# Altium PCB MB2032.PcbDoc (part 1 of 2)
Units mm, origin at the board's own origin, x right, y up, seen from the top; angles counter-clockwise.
Board outline 43.1 x 54.35 mm, 4 copper layers (Top Layer, Internal 1, Internal 2, Bottom Layer), stack 1.614 mm thick; 112 components, 86 nets, 372 pads, 581 vias.
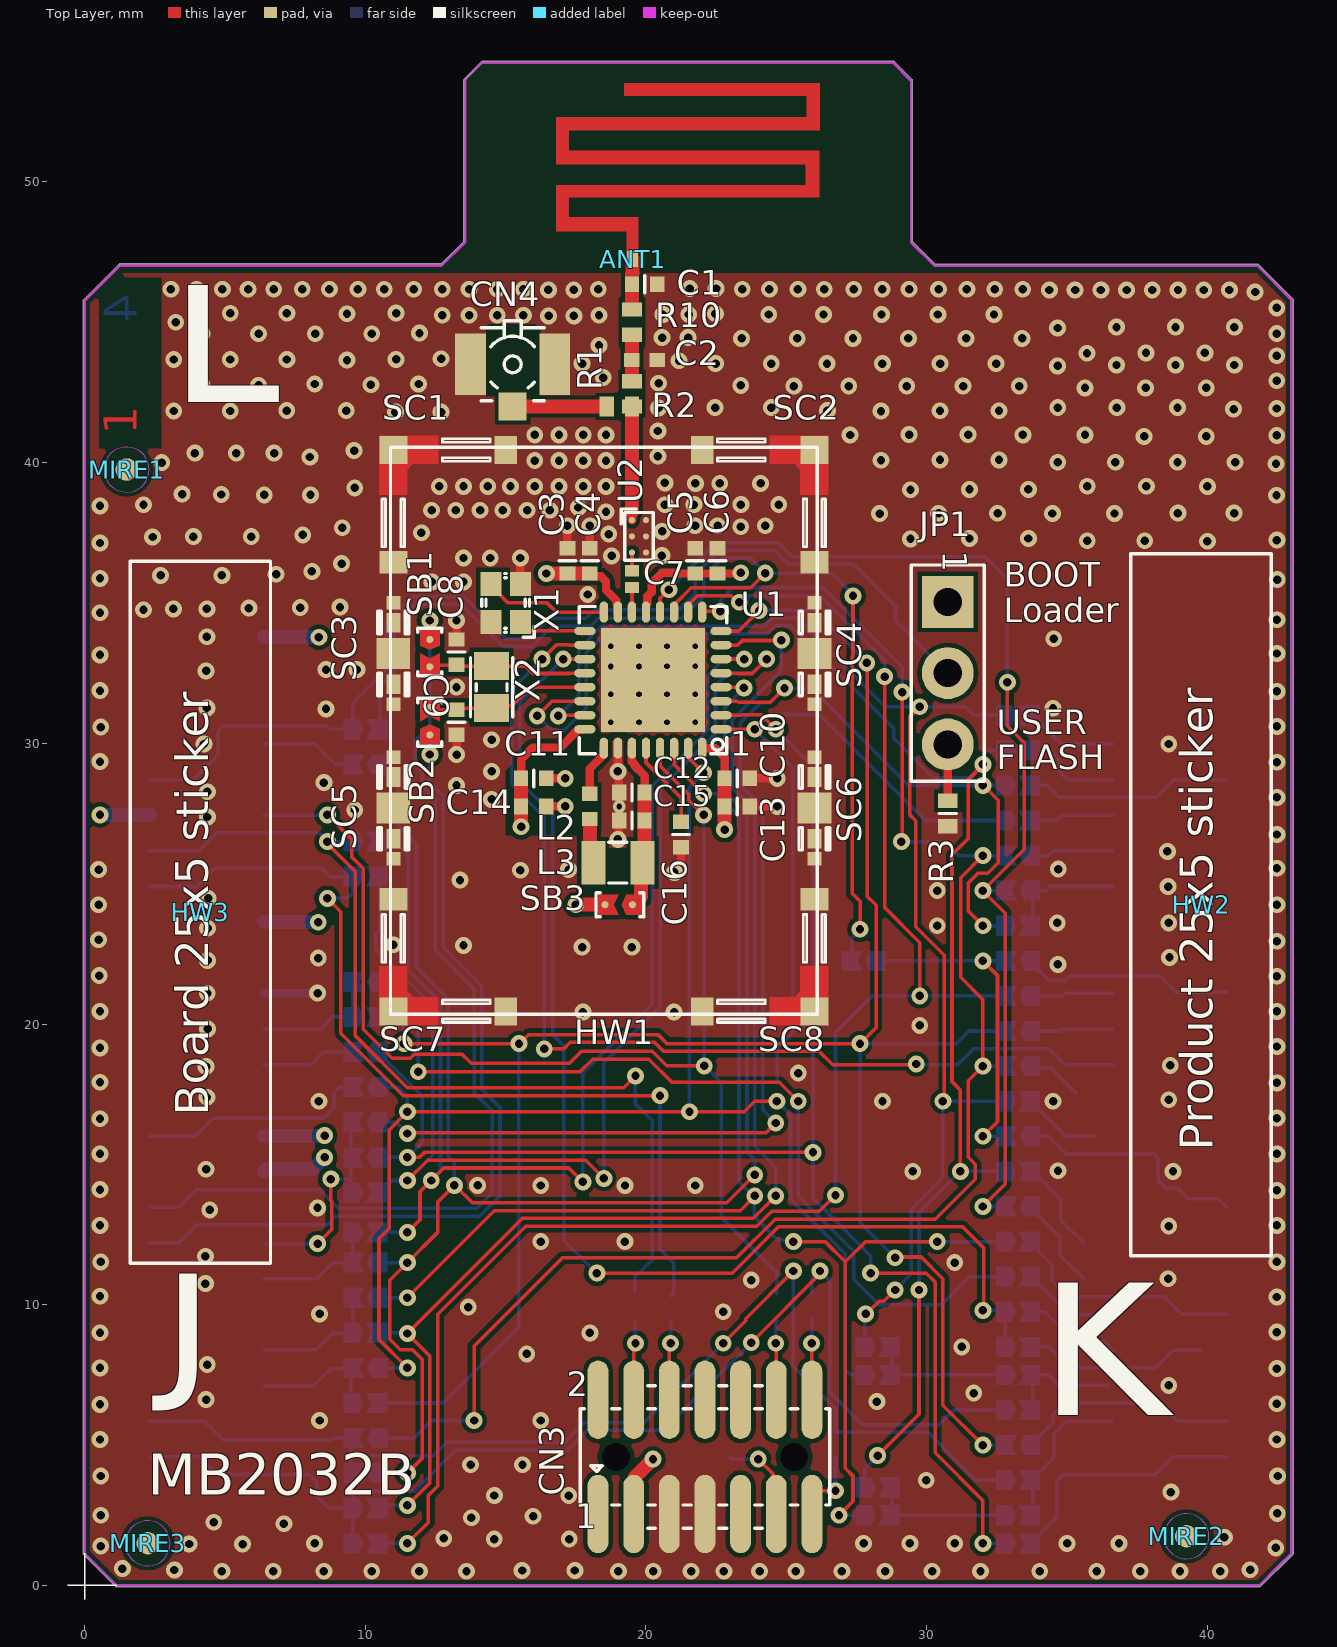
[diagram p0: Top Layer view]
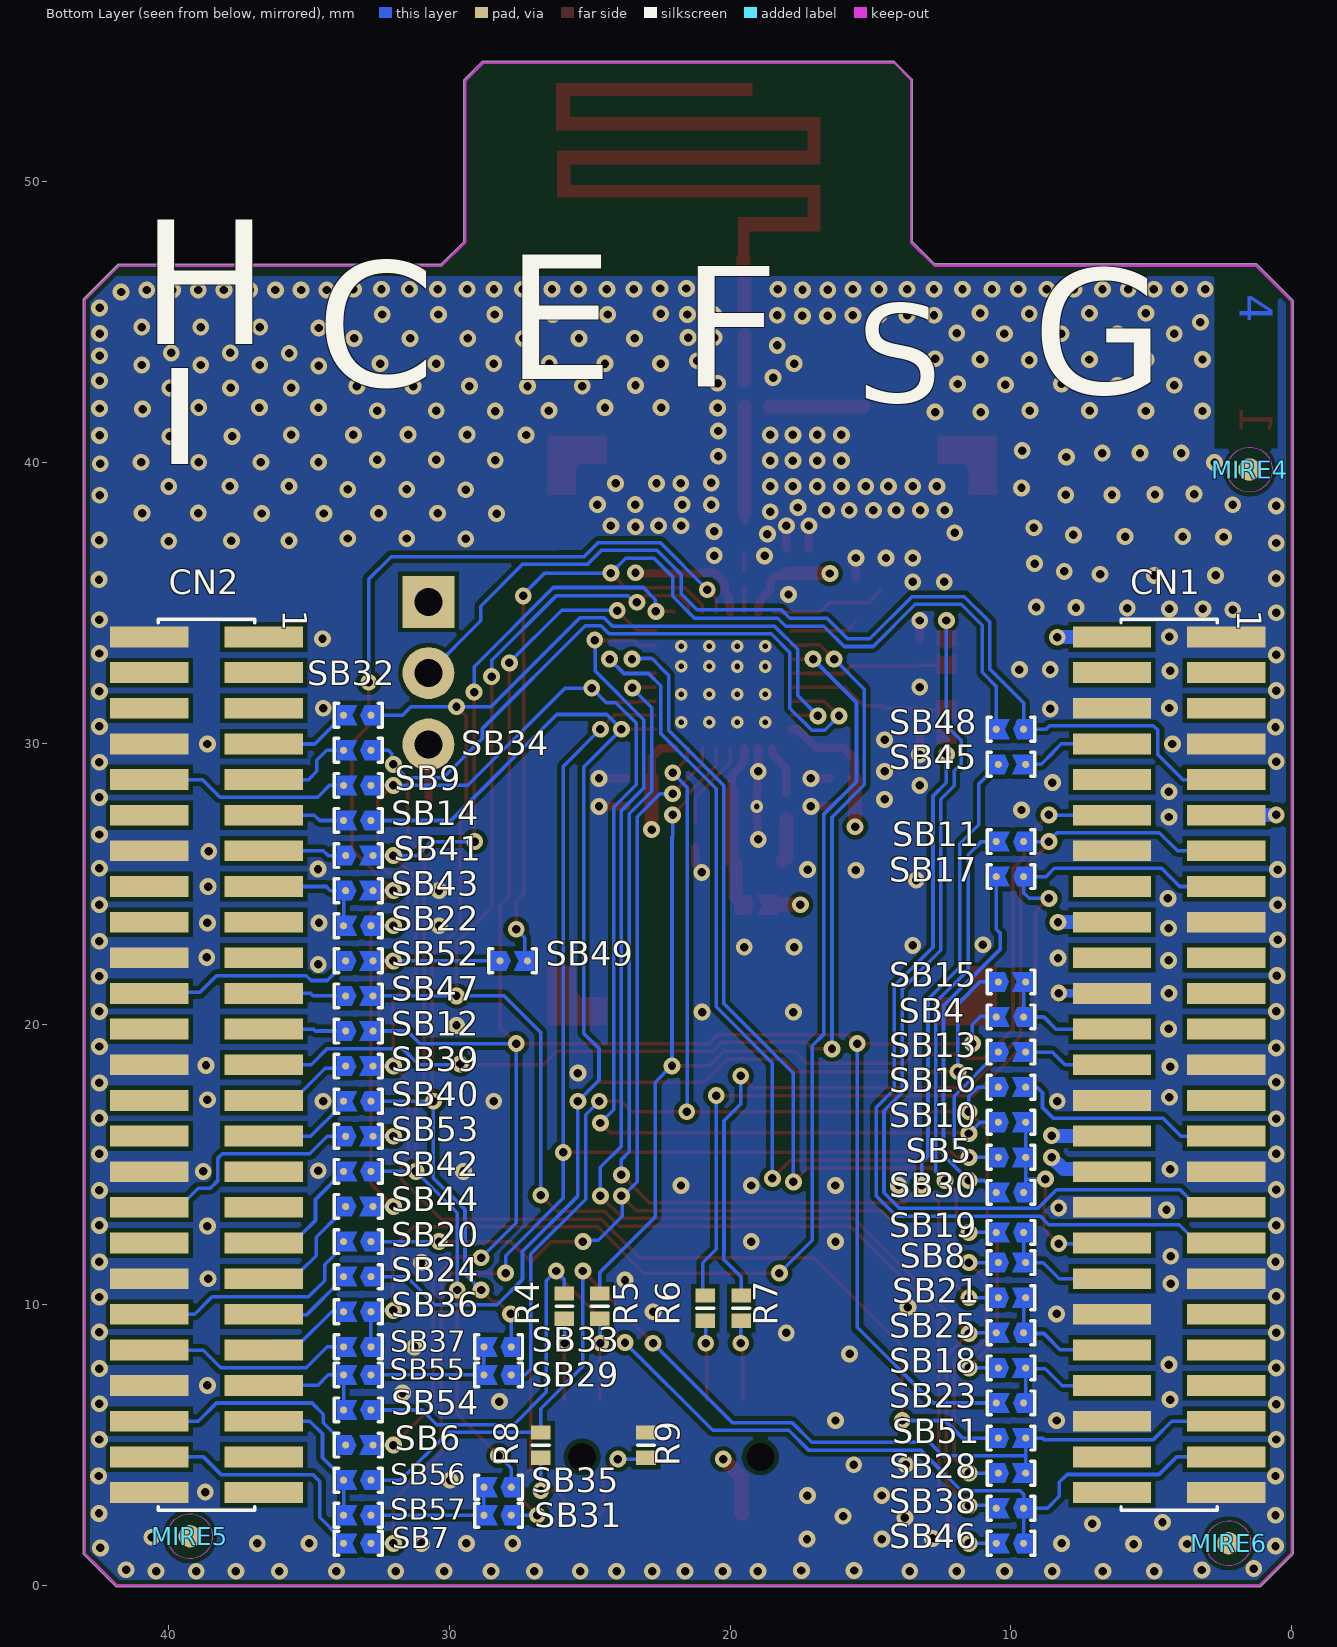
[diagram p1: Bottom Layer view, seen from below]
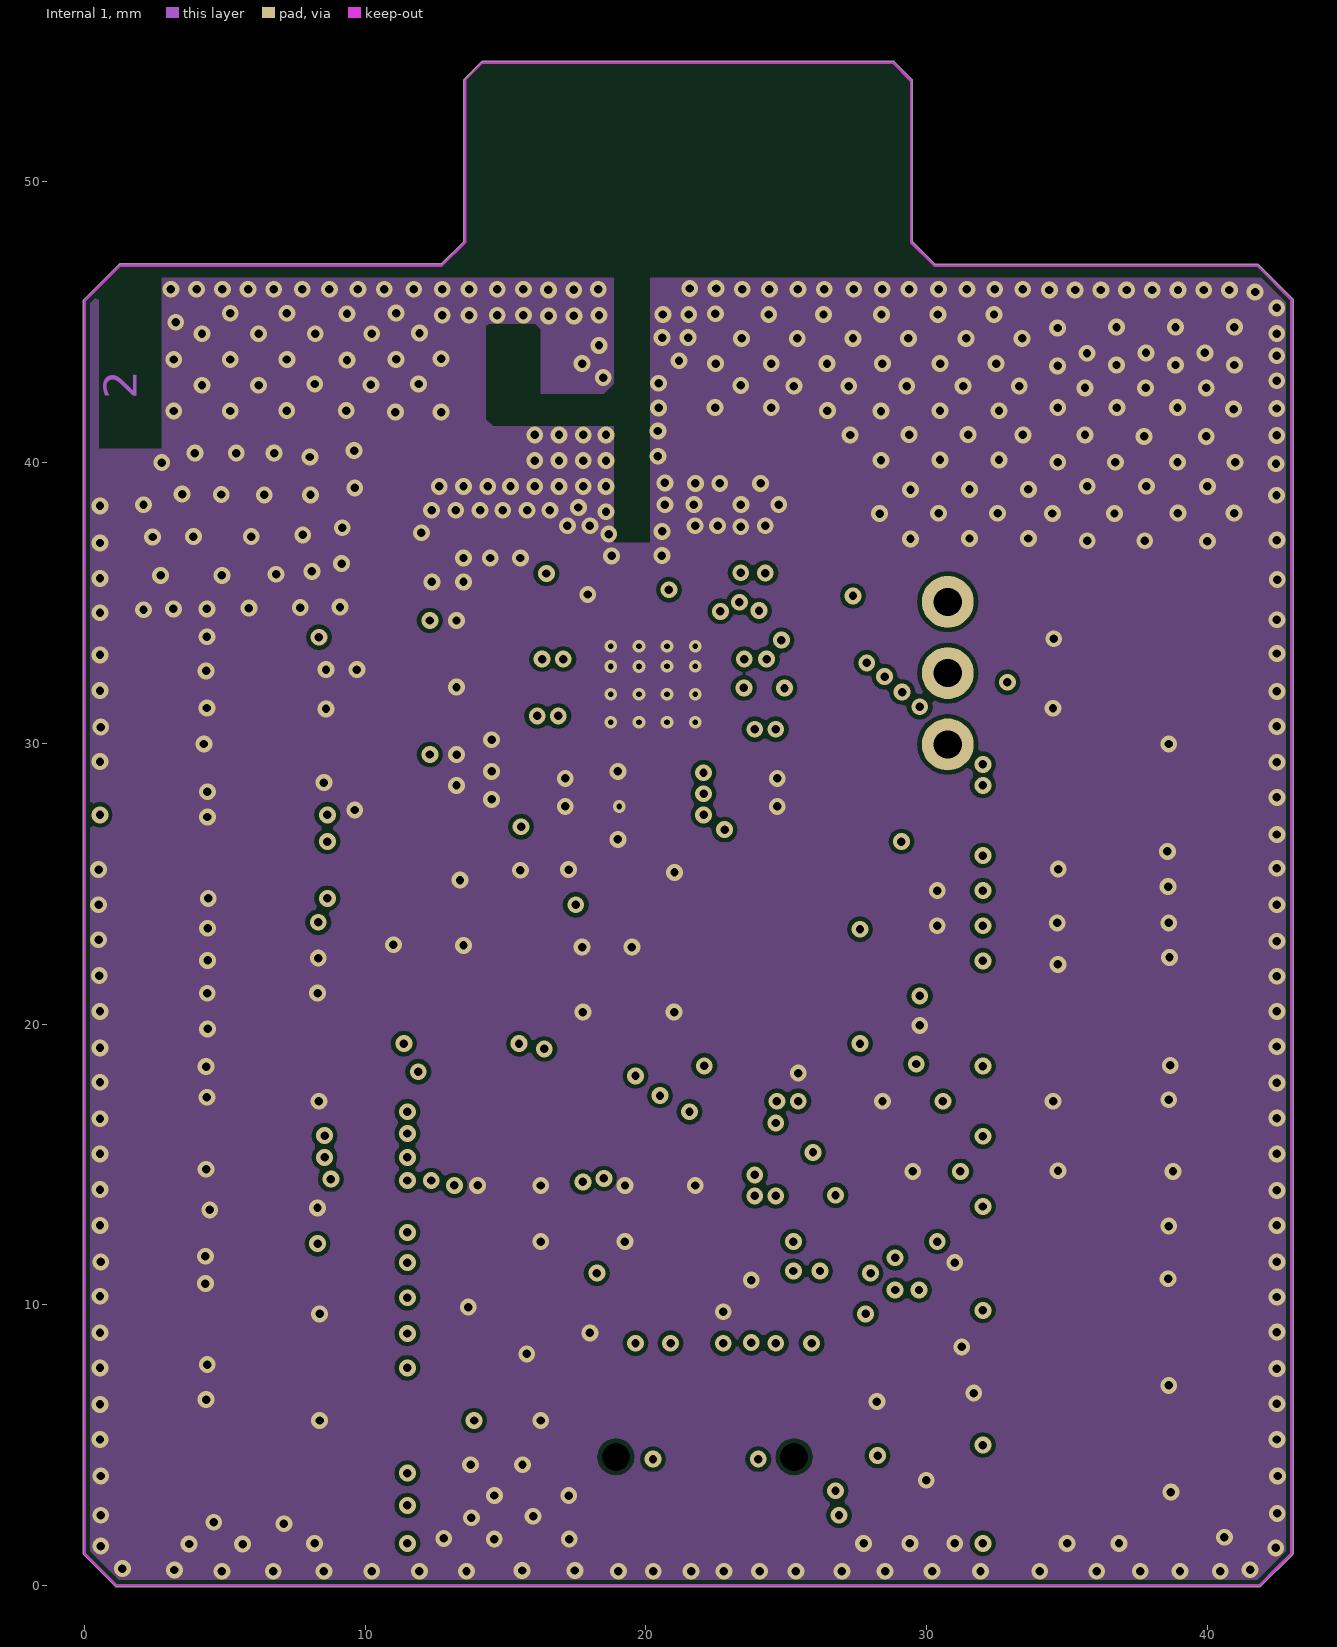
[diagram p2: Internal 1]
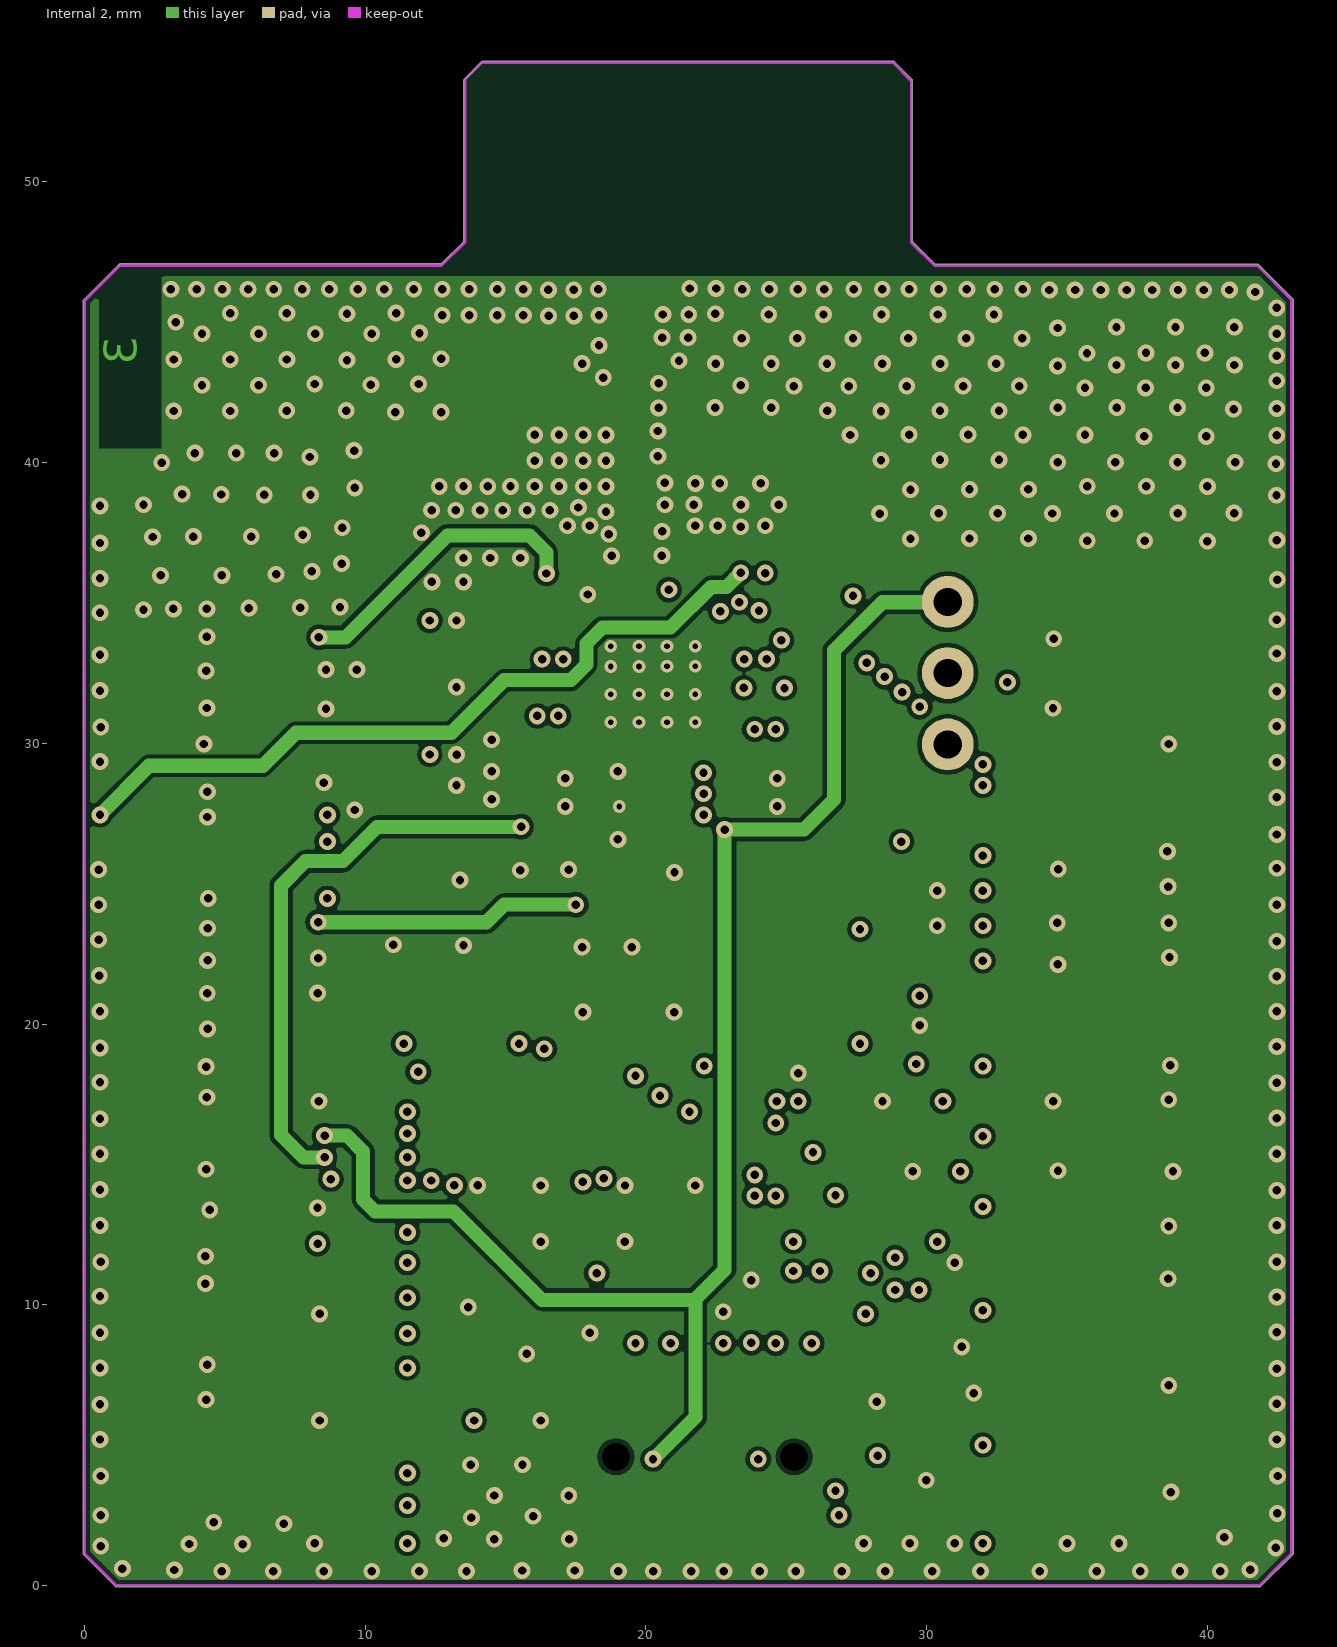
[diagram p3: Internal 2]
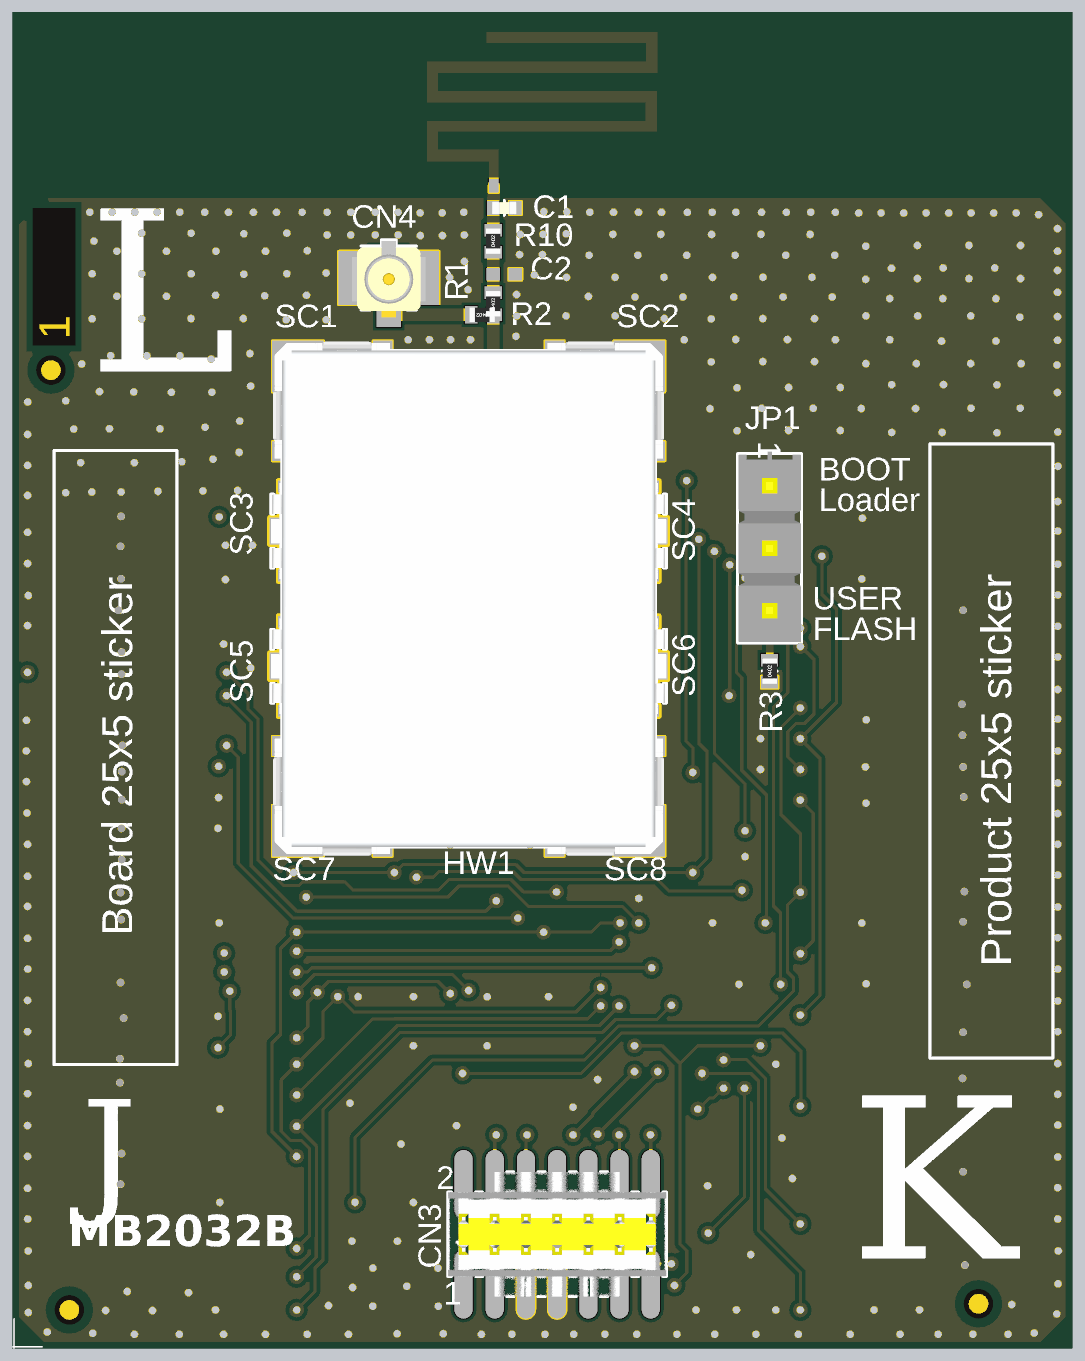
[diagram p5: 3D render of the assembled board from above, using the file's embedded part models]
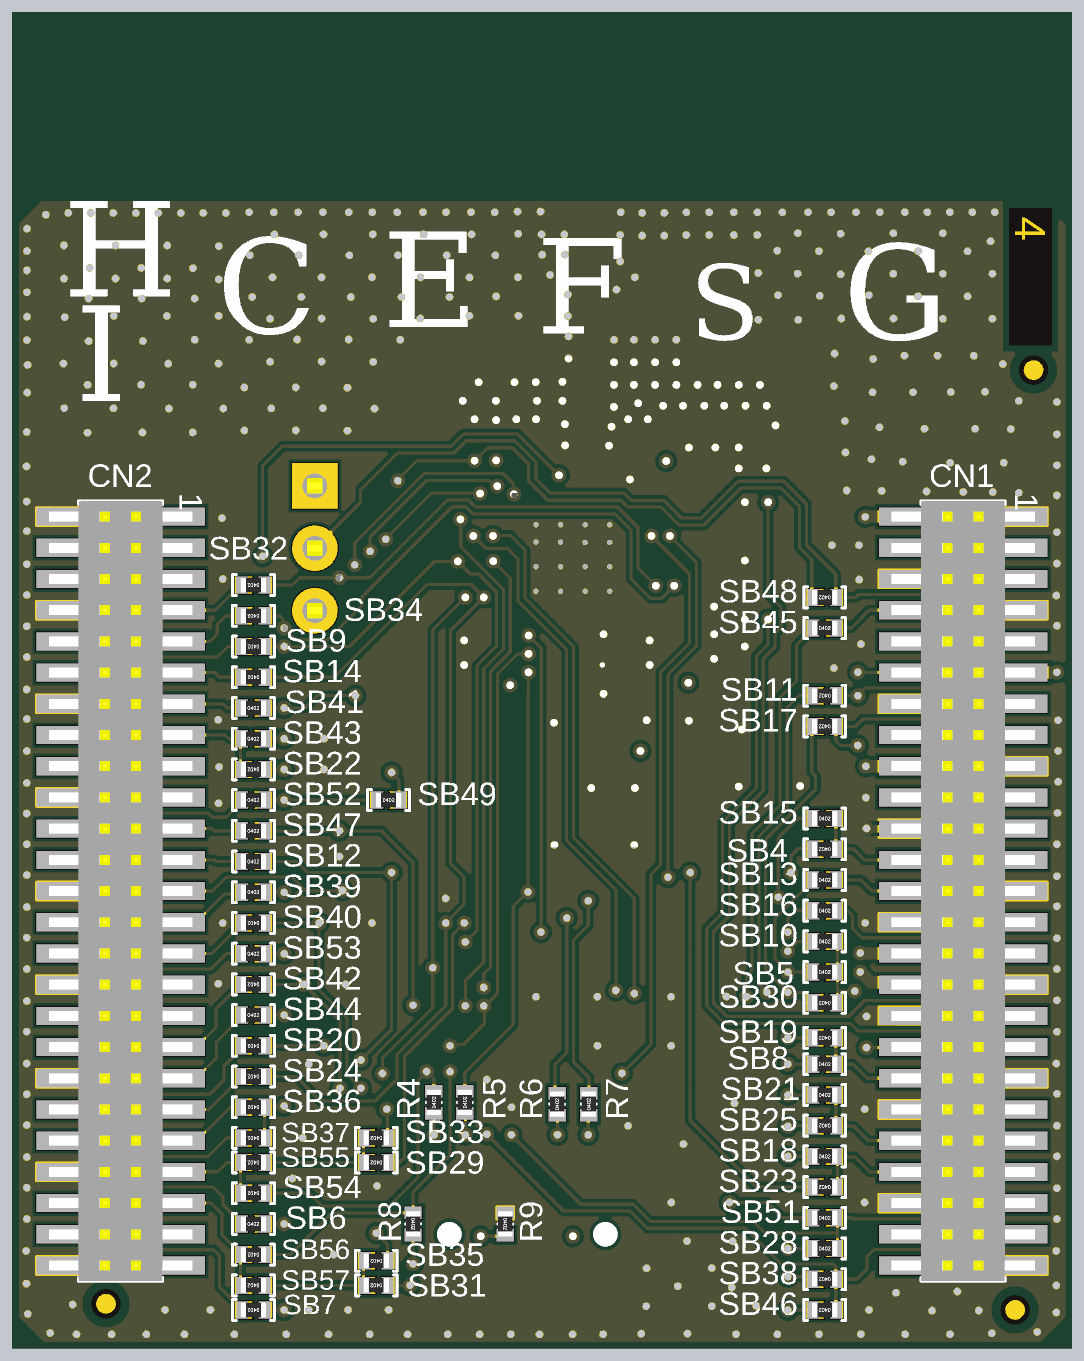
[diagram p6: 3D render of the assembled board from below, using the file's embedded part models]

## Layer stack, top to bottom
Top Solder: solder mask 0.015, Solder Resist, Dk 3.5
Top Layer: signal copper 0.042
Dielectric 1: core 0.106, FR-4, Dk 4.2
Internal 1: signal copper 0.035
Dielectric 3: prepreg 1.248, Dk 4.2
Internal 2: signal copper 0.035
Dielectric 2: core 0.106, Dk 4.2
Bottom Layer: signal copper 0.042
Bottom Solder: solder mask 0.015, Solder Resist, Dk 3.5

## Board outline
-0.05,1.139 -0.05,45.75 -0.05,45.755 cw(c0,45.755) -0.035,45.791 1.209,47.036 cw(c1.245,47) 1.218,47.042 cw(c1.26,47.015) 1.225,47.051 1.246,47.072 cw(c1.282,47.037) 1.282,47.087 12.721,47.087 13.512,47.878 13.512,53.615 cw(c13.563,53.615) 13.527,53.651 14.162,54.285 cw(c14.197,54.25) 14.198,54.3 28.803,54.3 cw(c28.803,54.25) 28.838,54.285 29.473,53.651 cw(c29.438,53.615) 29.488,53.615 29.488,47.876 30.293,47.071 cw(c30.257,47.035) 30.298,47.066 41.78,47.066 cw(c41.78,47.015) 41.816,47.051 43.03,45.837 cw(c43.001,45.795) 43.051,45.795 cw(c43.001,45.795) 43.05,45.785 43.05,1.151 cw(c43.001,1.141) 43.051,1.141 cw(c43.001,1.141) 43.037,1.105 41.888,-0.036 cw(c41.852,0) 41.852,-0.05 1.139,-0.05 cw(c1.139,0) 1.103,-0.036 -0.036,1.103 cw(c0,1.139)

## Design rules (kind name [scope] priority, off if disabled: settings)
Clearance RF_C4 [InNet('NetC4_1') or  InNet('NetC4_2') vs InNet('GND')] p1: gap=0.1 ignorepadtopadclearanceinfootprint=FALSE except(0.145: Arc-Text Track-Text SMDPad-SMDPad SMDPad-THPad SMDPad-Via SMDPad-Text THPad-THPad THPad-Via THPad-Text Via-Via Via-Text Fill-Text Poly-Text Region-Text Text-Text; 0.2: Arc-Hole Track-Hole SMDPad-Hole THPad-Hole Via-Hole Fill-Hole Poly-Hole Region-Hole Text-Hole)
Clearance RF_signals [InNetClass('NC_SINGLE_50_OHMS') vs InNet('GND')] p2: gap=0.145 ignorepadtopadclearanceinfootprint=FALSE except(0.138: Arc-Fill Arc-Poly Arc-Region Track-Fill Track-Poly Track-Region; 0.2: Arc-Hole Track-Hole SMDPad-Hole THPad-Hole Via-Hole Fill-Hole Poly-Hole Region-Hole Text-Hole)
Clearance [All] p3: gap=0.15 ignorepadtopadclearanceinfootprint=FALSE
ComponentClearance [All] p1: gap=0.2 collisioncheckmode=3 verticalgap=0.2 showdistances=FALSE
HoleSize [All] p1: absolutevalues=TRUE maxlimit=10 minlimit=0.025 maxpercent=80.000 minpercent=20.000
MinimumSolderMaskSliver [All] p1: minsoldermaskwidth=0.1
PlaneConnect [All] p1: planeconnectstyle=Relief reliefexpansion=0.508 reliefentries=4 reliefconductorwidth=0.21 reliefairgap=0.21
PolygonConnect PolygonConnect_via [IsVia] p1: connectstyle=Direct reliefconductorwidth=0.254 reliefentries=4 polygonreliefangle="90 Angle" airgapwidth=0.254
PolygonConnect General [All] p2: connectstyle=Direct reliefconductorwidth=0.2 reliefentries=4 polygonreliefangle="90 Angle" airgapwidth=0.2
RoutingVias [All] p1: holewidth=0.3 width=0.6 viastyle="Through Hole" minholewidth=0.2 minwidth=0.5 maxholewidth=3.5 maxwidth=6.5
SilkToSilkClearance [All] p1: silktosilkclearance=0.2
SilkToSolderMaskClearance [IsPad] p1: minsilkscreentomaskgap=0.2 clearancetoexposedcopper=TRUE
SolderMaskExpansion [All] p1: expansion=0.102 istentingtop=FALSE
Width Width_RF [InNetClass('NC_SINGLE_50_OHMS')] p1: maxlimit=0.5 minlimit=0.254 preferedwidth=0.254 toplayer_minwidth=0.28 toplayer_prefwidth=0.5 impedanceprofiledriven=TRUE minimp=50.000000 maximp=50.000000 favimp=50.000000
Width [All] p2: maxlimit=6 minlimit=0.127 preferedwidth=0.5 toplayer_prefwidth=0.127 midlayer1_minwidth=0.21 midlayer1_maxwidth=0.8 midlayer1_prefwidth=0.254 midlayer2_minwidth=0.21 midlayer2_maxwidth=0.8 bottomlayer_prefwidth=0.127 minimp=50.000000 maximp=50.000000 favimp=50.000000
24 further rules are at their usual default settings.

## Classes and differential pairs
net class NC_SINGLE_50_OHMS: NetANT1_1 NetC2_2 NetCN4_1 NetR1_1
component class U_RF: ANT1 C1 C2 C3 C4 C7 CN4 HW1 R1 R2 R10 SC1 SC2 SC3 SC4 SC5 SC6 SC7 SC8 U1 U2 X1
component class U_Connectors: CN1 CN2 SB52 SB53 SB54 SB55 SB56 SB57
component class U_MCU: C8 C9 CN3 JP1 R3 R4 R5 R6 R7 R8 R9 SB1 SB2 SB4 SB5 SB6 SB7 SB8 SB9 SB10 SB11 SB12 SB13 SB14 SB15 SB16 SB17 SB18 SB19 SB20 SB21 SB22 SB23 SB24 SB25 SB28 SB29 SB30 SB31 SB32 SB33 SB34 SB35 SB36 SB37 SB38 SB39 SB40 SB41 SB42 SB43 SB44 SB45 SB46 SB47 SB48 SB49 SB51 X2
component class U_Power_Supply: C5 C6 C10 C11 C12 C13 C14 C15 C16 L2 L3 SB3
component class Project_Overview: HW2 HW3

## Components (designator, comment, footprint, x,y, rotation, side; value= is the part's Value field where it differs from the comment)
ANT1 "2.4GHz_BT_ANT" ANT_BT_BNRG_2P4GHZ_MB2032 19.38,47.25 r90 top value=2.4GHZ_BNRG_ANT
C1 "Capacitor" C0402 19.95,46.35 r180 top value=6.8pF
C2 "Capacitor" C0402_MURATA_GRM155_H0P5 19.95,43.65 r180 top value=0.9pF
C3 "Capacitor" C0402 17.2,36.5 r270 top value=100nF
C4 "Capacitor" C0402 18,36.5 r270 top value=3pF
C5 "Capacitor" C0402 21.75,36.5 r270 top value=3pF
C6 "Capacitor" C0402 22.55,36.5 r270 top value=100nF
C7 "Capacitor" C0201_H0P3 19.5,35.85 r90 top value=20pF
C8 "Capacitor" C0402 13.25,33.25 r270 top value=10pF
C9 "Capacitor" C0402 13.25,30.75 r270 top value=10pF
C10 "Capacitor" C0402 23.25,28.75 r180 top value=100nF
C11 "Capacitor" C0402 16,28.75 r180 top value=100nF
C12 "Capacitor" C0402 19.5,28.25 r0 top value=100nF
C13 "Capacitor" C0402 23.25,27.75 r180 top value=1uF
C14 "Capacitor" C0402 16,27.75 r180 top value=4.7uF
C15 "Capacitor" C0402 19.5,27.25 r0 top value=4.7uF
C16 "Capacitor" C0402 21.25,26.75 r90 top value=0.22uF
CN1 "FTSH-125-02-L-DV" CON_SAMTEC_FTSH-125-02-L-DV 4.366,18.548 r270 bottom value="Header 25x2"
CN2 "FTSH-125-02-L-DV" CON_SAMTEC_FTSH-125-02-L-DV 38.656,18.548 r270 bottom value="Header 25x2"
CN3 "Header 7x2" CON_SAMTEC_FTSH-107-01-L-DV-K-A 22.101,4.579 r0 top
CN4 "U.FL-R-SMT-1" CON_HRS_U.FL-R-SMT-1 15.25,43.5 r0 top value=Con_RF_U.FL-R-SMT-1
Designator1 "Comment" IMPEDANCE_TABLE -4.013,161.315 r0 top
Designator2 "Comment" PCB_SPECIFICATIONS -3.124,121.133 r0 top
Designator3 "Comment" Sheetbox_4L2S 51.892,-13.183 r0 top
HW1 "S02-20150300" SHIELD_HARWIN_S02-20150300_15X20_H3 18.5,30.45 r0 top
HW2 "STICKER_PRODUCT" STICKER_PRODUCT_25X5 39.775,24.249 r90 top value="Sticker product"
HW3 "STICKER_BOARD" STICKER_BOARD_25X5 4.126,23.98 r90 top value="Sticker board"
JP1 "Jumper_Header 3x1 Fitted 2-3" CON_SAMTEC_TSW-103-07-F-S 30.75,32.5 r270 top value="Header 3x1"
L2 "Inductor" C0402 18,27.75 r90 top value=22nH
L3 "Inductor" IND_0805_MURATA_LQM21 19,25.75 r180 top value=10uH
MIRE1 "Comment" MIRE_PLACE_SMD_0P8MM 1.5,39.75 r0 top
MIRE2 "Comment" MIRE_PLACE_SMD_0P8MM 39.25,1.75 r0 top
MIRE3 "Comment" MIRE_PLACE_SMD_0P8MM 2.25,1.5 r0 top
MIRE4 "Comment" MIRE_PLACE_SMD_0P8MM 1.5,39.75 r0 bottom
MIRE5 "Comment" MIRE_PLACE_SMD_0P8MM 39.25,1.75 r0 bottom
MIRE6 "Comment" MIRE_PLACE_SMD_0P8MM 2.25,1.5 r0 bottom
R1 "Resistor" R0402 19.5,42.45 r90 top value=0R
R2 "Resistor" r0402 19.05,42 r180 top value=0R
R3 "Resistor" R0402 30.75,27.5 r90 top value=100K
R4 "Resistor" R0402 25.909,9.947 r90 bottom value=47R
R5 "Resistor" R0402 24.651,9.947 r90 bottom value=47R
R6 "Resistor" R0402 20.887,9.878 r90 bottom value=47R
R7 "Resistor" R0402 19.605,9.878 r90 bottom value=47R
R8 "Resistor" R0402 26.75,5 r270 bottom value=47R
R9 "Resistor" R0402 23,5 r270 bottom value=100R
R10 "Resistor" R0402 19.5,45 r90 top value=0R
SB1 "SB_ON" SOLDER-BRIDGE_R0402-0R 12.3,33.25 r270 top value="0 ohm"
SB2 "SB_ON" SOLDER-BRIDGE_R0402-0R 12.3,30.75 r90 top value="0 ohm"
SB3 "SB_ON" SOLDER-BRIDGE_R0402-0R 19.069,24.25 r180 top
SB4 "SB_ON" SOLDER-BRIDGE_R0402-0R 10,20.25 r0 bottom value="0 ohm"
SB5 "SB_ON" SOLDER-BRIDGE_R0402-0R 10,15.25 r180 bottom value="0 ohm"
SB6 "SB_ON" SOLDER-BRIDGE_R0402-0R 33.25,5 r180 bottom value="0 ohm"
SB7 "SB_ON" SOLDER-BRIDGE_R0402-0R 33.25,1.5 r0 bottom value="0 ohm"
SB8 "SB_ON" SOLDER-BRIDGE_R0402-0R 10,11.5 r180 bottom value="0 ohm"
SB9 "SB_ON" SOLDER-BRIDGE_R0402-0R 33.25,28.5 r0 bottom value="0 ohm"
SB10 "SB_ON" SOLDER-BRIDGE_R0402-0R 10,16.5 r180 bottom value="0 ohm"
SB11 "SB_ON" SOLDER-BRIDGE_R0402-0R 10,26.5 r0 bottom value="0 ohm"
SB12 "SB_ON" SOLDER-BRIDGE_R0402-0R 33.25,19.75 r180 bottom value="0 ohm"
SB13 "SB_ON" SOLDER-BRIDGE_R0402-0R 10,19 r180 bottom value="0 ohm"
SB14 "SB_ON" SOLDER-BRIDGE_R0402-0R 33.25,27.25 r0 bottom value="0 ohm"
SB15 "SB_ON" SOLDER-BRIDGE_R0402-0R 10,21.5 r180 bottom value="0 ohm"
SB16 "SB_ON" SOLDER-BRIDGE_R0402-0R 10,17.75 r180 bottom value="0 ohm"
SB17 "SB_ON" SOLDER-BRIDGE_R0402-0R 10,25.25 r0 bottom value="0 ohm"
SB18 "SB_ON" SOLDER-BRIDGE_R0402-0R 10,7.75 r180 bottom value="0 ohm"
SB19 "SB_ON" SOLDER-BRIDGE_R0402-0R 10,12.575 r0 bottom value="0 ohm"
SB20 "SB_ON" SOLDER-BRIDGE_R0402-0R 33.25,12.25 r0 bottom value="0 ohm"
SB21 "SB_ON" SOLDER-BRIDGE_R0402-0R 10,10.25 r180 bottom value="0 ohm"
SB22 "SB_ON" SOLDER-BRIDGE_R0402-0R 33.25,23.5 r0 bottom value="0 ohm"
SB23 "SB_ON" SOLDER-BRIDGE_R0402-0R 10,6.5 r0 bottom value="0 ohm"
SB24 "SB_ON" SOLDER-BRIDGE_R0402-0R 33.25,11 r0 bottom value="0 ohm"
SB25 "SB_ON" SOLDER-BRIDGE_R0402-0R 10,9 r0 bottom value="0 ohm"
SB28 "SB_ON" SOLDER-BRIDGE_R0402-0R 10,4 r180 bottom value="0 ohm"
SB29 "SB_ON" SOLDER-BRIDGE_R0402-0R 28.25,7.5 r0 bottom value="0 ohm"
SB30 "SB_ON" SOLDER-BRIDGE_R0402-0R 10,14 r0 bottom value="0 ohm"
SB31 "SB_ON" SOLDER-BRIDGE_R0402-0R 28.25,2.5 r0 bottom value="0 ohm"
SB32 "SB_ON" SOLDER-BRIDGE_R0402-0R 33.25,31 r0 bottom value="0 ohm"
SB33 "SB_ON" SOLDER-BRIDGE_R0402-0R 28.25,8.5 r0 bottom value="0 ohm"
SB34 "SB_ON" SOLDER-BRIDGE_R0402-0R 33.25,29.75 r0 bottom value="0 ohm"
SB35 "SB_ON" SOLDER-BRIDGE_R0402-0R 28.25,3.5 r0 bottom value="0 ohm"
SB36 "SB_ON" SOLDER-BRIDGE_R0402-0R 33.25,9.75 r0 bottom value="0 ohm"
SB37 "SB_ON" SOLDER-BRIDGE_R0402-0R 33.25,8.5 r0 bottom value="0 ohm"
SB38 "SB_ON" SOLDER-BRIDGE_R0402-0R 10,2.75 r0 bottom value="0 ohm"
SB39 "SB_ON" SOLDER-BRIDGE_R0402-0R 33.25,18.5 r180 bottom value="0 ohm"
SB40 "SB_ON" SOLDER-BRIDGE_R0402-0R 33.25,17.25 r0 bottom value="0 ohm"
SB41 "SB_ON" SOLDER-BRIDGE_R0402-0R 33.25,26 r180 bottom value="0 ohm"
SB42 "SB_ON" SOLDER-BRIDGE_R0402-0R 33.25,14.75 r0 bottom value="0 ohm"
SB43 "SB_ON" SOLDER-BRIDGE_R0402-0R 33.25,24.75 r180 bottom value="0 ohm"
SB44 "SB_ON" SOLDER-BRIDGE_R0402-0R 33.25,13.5 r180 bottom value="0 ohm"
SB45 "SB_ON" SOLDER-BRIDGE_R0402-0R 10,29.25 r180 bottom value="0 ohm"
SB46 "SB_ON" SOLDER-BRIDGE_R0402-0R 10,1.5 r0 bottom value="0 ohm"
SB47 "SB_ON" SOLDER-BRIDGE_R0402-0R 33.25,21 r180 bottom value="0 ohm"
SB48 "SB_ON" SOLDER-BRIDGE_R0402-0R 10,30.5 r0 bottom value="0 ohm"
SB49 "SB_ON" SOLDER-BRIDGE_R0402-0R 27.75,22.25 r180 bottom value="0 ohm"
SB51 "SB_ON" SOLDER-BRIDGE_R0402-0R 10,5.25 r180 bottom value="0 ohm"
SB52 "SB_ON" SOLDER-BRIDGE_R0402-0R 33.25,22.25 r180 bottom value="0 ohm"
SB53 "SB_ON" SOLDER-BRIDGE_R0402-0R 33.25,16 r180 bottom value="0 ohm"
SB54 "SB_ON" SOLDER-BRIDGE_R0402-0R 33.25,6.25 r0 bottom value="0 ohm"
SB55 "SB_ON" SOLDER-BRIDGE_R0402-0R 33.25,7.5 r0 bottom value="0 ohm"
SB56 "SB_ON" SOLDER-BRIDGE_R0402-0R 33.25,3.75 r0 bottom value="0 ohm"
SB57 "SB_ON" SOLDER-BRIDGE_R0402-0R 33.25,2.5 r0 bottom value="0 ohm"
SC1 "Shield-clip_S0951-46R" CLIP_HARWIN_S0981-46R 11,40.45 r180 top value=S0981-46R
SC2 "Shield-clip_S0951-46R" CLIP_HARWIN_S0981-46R 26,40.45 r90 top value=S0981-46R
SC3 "Shield-clip_S0951-46R" CLIP_HARWIN_S0951-46R 11,33.2 r90 top value=S0951-46R
SC4 "Shield-clip_S0951-46R" CLIP_HARWIN_S0951-46R 26,33.2 r90 top value=S0951-46R
SC5 "Shield-clip_S0951-46R" CLIP_HARWIN_S0951-46R 11,27.7 r90 top value=S0951-46R
SC6 "Shield-clip_S0951-46R" CLIP_HARWIN_S0951-46R 26,27.7 r90 top value=S0951-46R
SC7 "Shield-clip_S0951-46R" CLIP_HARWIN_S0981-46R 11,20.45 r270 top value=S0981-46R
SC8 "Shield-clip_S0951-46R" CLIP_HARWIN_S0981-46R 26,20.45 r0 top value=S0981-46R
U1 "STM32WB09" ICC_QFN32-EPAD_5X5_P050 20.25,32.25 r90 top
U2 "MLPF-WB55-01E3" ICC_CSPG_6BUMPS_1X1P60_P050-P0577 19.75,37.372 r0 top value=MLPF-NRG-01D3
X1 "XTAL_4_PINS" CRY_NX2016SA_4P 15,35 r90 top value=32MHz
X2 "XTAL_2_PINS" CRY_NX2012SA_2P 14.5,32 r90 top value=32.768kHz

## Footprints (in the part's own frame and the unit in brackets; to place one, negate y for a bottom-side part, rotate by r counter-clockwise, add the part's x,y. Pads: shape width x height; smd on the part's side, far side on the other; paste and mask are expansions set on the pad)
ANT_BT_BNRG_2P4GHZ_MB2032 [mm] "MCD-03495"
  rect 0.56x0.4 smd mask+0.05: 1(0,-0.14)
  Top Layer region: 4.585,-6.816 4.585,2.134 3.86,2.134 3.86,-6.791 2.21,-6.791 2.21,2.134 1.485,2.134 1.485,-0.341 -0.14,-0.341 -0.165,-0.341 -0.165,0.059 0.985,0.059 0.985,2.584 2.61,2.584 2.635,2.584 2.635,-6.316 3.01,-6.316 3.385,-6.316 3.385,2.584 5.01,2.584 5.06,2.584 5.06,-6.341 5.81,-6.341 5.81,0.159 6.26,0.159 6.26,-6.816
  body extent 1.11,-0.88 1.75,-0.54, height 0.33
C0201_H0P3 [mm] "MCD-00699"
  rect 0.4x0.5 smd mask+0.05: 1(-0.3,0) 2(0.3,0)
  body extent -0.32,-0.17 0.32,0.17, height 0.33
C0402 [mm]
  rect 0.51x0.56 smd mask+0.05: 1(-0.45,0) 2(0.45,0)
  silkscreen extent 0,-0.3 0,0.3, body extent -0.5,-0.3 0.5,0.3, height 0.4
C0402_MURATA_GRM155_H0P5 [mm] "MCD-03662"
  rect 0.55x0.5 smd mask+0.05: 1(-0.45,0) 2(0.45,0)
  body extent -0.53,-0.28 0.53,0.27, height 0.55
CLIP_HARWIN_S0951-46R [mm] "MCD-01587_CLIP-X1"
  rect 0.48x0.5 smd mask+0.1: 1(-1.81,0) 1(1.81,0)
  rect 0.7x0.5 smd mask+0.1: 1(-1.1,0) 1(1.1,0)
  rect 1.1x1.2 smd mask+0.1: 1(0,0)
  silkscreen extent -1.5,-0.55 1.5,0.55, body extent -2.05,-0.65 2.05,0.65, height 1.28
CLIP_HARWIN_S0981-46R [mm] "MCD-02164"
  rect 0.8x1 smd mask+0.05: 1(-4,0)
  rect 1x0.8 smd mask+0.05: 1(0,4)
  rect 1x1 smd mask+0.05: 1(0,0)
  Top Layer region: -1.6,-0.5 0.5,-0.5 0.5,1.6 -0.5,1.6 -0.5,0.7 -0.7,0.5 -1.6,0.5
  silkscreen extent -3.45,-0.4 0.4,3.45, body extent -4.3,-0.46 0.46,4.3, height 1.4
CON_HRS_U.FL-R-SMT-1 [mm] "MCD-01583"
  rect 1x1 smd mask+0.05: 1(0,-1.5)
  rect 1.1x2.2 smd mask+0.05: 2(-1.5,0) 3(1.5,0)
  silkscreen extent -1.12,-1.3 1.12,1.55, body extent -1.5,-1.6 1.5,1.5, height 1.25
CON_SAMTEC_FTSH-107-01-L-DV-K-A [mm] "MCD-01959"
  oval 0.74x2.79 smd mask+0.05: 1(-3.81,-2.035) 2(-3.81,2.035) 3(-2.54,-2.035) 4(-2.54,2.035) 5(-1.27,-2.035) 6(-1.27,2.035) 7(0,-2.035) 8(0,2.035) 9(1.27,-2.035) 10(1.27,2.035) 11(2.54,-2.035) 12(2.54,2.035) 13(3.81,-2.035) 14(3.81,2.035)
  round 0 hole 1 unplated paste-10 mask+0.05: NPTH1(-3.175,0) NPTH2(3.175,0)
  silkscreen extent -4.44,-2.54 4.44,2.54, body extent -4.44,-2.92 4.45,2.92, height 6.12
CON_SAMTEC_FTSH-125-02-L-DV [mm]
  rect 0.74x2.79 smd mask+0.05: 1(-15.24,2.035) 2(-15.24,-2.035) 3(-13.97,2.035) 4(-13.97,-2.035) 5(-12.7,2.035) 6(-12.7,-2.035) 7(-11.43,2.035) 8(-11.43,-2.035) 9(-10.16,2.035) 10(-10.16,-2.035) 11(-8.89,2.035) 12(-8.89,-2.035) 13(-7.62,2.035) 14(-7.62,-2.035) 15(-6.35,2.035) 16(-6.35,-2.035) 17(-5.08,2.035) 18(-5.08,-2.035) 19(-3.81,2.035) 20(-3.81,-2.035) 21(-2.54,2.035) 22(-2.54,-2.035) 23(-1.27,2.035) 24(-1.27,-2.035) 25(0,2.035) 26(0,-2.035) 27(1.27,2.035) 28(1.27,-2.035) 29(2.54,2.035) 30(2.54,-2.035) 31(3.81,2.035) 32(3.81,-2.035) 33(5.08,2.035) 34(5.08,-2.035) 35(6.35,2.035) 36(6.35,-2.035) 37(7.62,2.035) 38(7.62,-2.035) 39(8.89,2.035) 40(8.89,-2.035) 41(10.16,2.035) 42(10.16,-2.035) 43(11.43,2.035) 44(11.43,-2.035) 45(12.7,2.035) 46(12.7,-2.035) 47(13.97,2.035) 48(13.97,-2.035) 49(15.24,2.035) 50(15.24,-2.035)
  silkscreen extent -15.88,-1.71 15.88,1.71, body extent -15.87,-2.92 15.88,2.92, height 4.82
CON_SAMTEC_TSW-103-07-F-S [mm]
  rect 1.85x1.85 / inner round 1.85 / far side rect 1.85x1.85 hole 1 mask+0.05: 1(-2.54,0)
  round 1.85 hole 1 mask+0.05: 2(0,0) 3(2.54,0)
  silkscreen extent -3.85,-1.3 3.85,1.3, body extent -3.94,-1.37 3.91,1.37, height 8.38
CRY_NX2012SA_2P [mm]
  rect 1x1.25 smd mask+0.05: 1(-0.75,0) 2(0.75,0)
  silkscreen extent -1.05,-0.75 1.05,0.75, body extent -1.05,-0.63 1.05,0.63, height 0.6
CRY_NX2016SA_4P [mm]
  rect 0.85x0.75 smd mask+0.05: 1(-0.675,-0.525) 2(0.675,-0.525) 3(0.675,0.525) 4(-0.675,0.525)
  silkscreen extent -1.22,-1.02 1.05,0.85, body extent -1.05,-0.85 1.05,0.85, height 0.7
ICC_CSPG_6BUMPS_1X1P60_P050-P0577 [mm] "MCD-03490"
  round 0.22 smd paste+0 mask+0: A1(-0.25,0.577) A2(-0.25,0) A3(-0.25,-0.577) B1(0.25,0.577) B2(0.25,0) B3(0.25,-0.577)
  silkscreen extent -0.64,-0.85 0.51,0.97, body extent -0.51,-0.81 0.51,0.81, height 0.7
ICC_QFN32-EPAD_5X5_P050 [mm]
  oval 0.3x0.75 smd mask+0.05: 1(-1.75,-2.425) 2(-1.25,-2.425) 3(-0.75,-2.425) 4(-0.25,-2.425) 5(0.25,-2.425) 6(0.75,-2.425) 7(1.25,-2.425) 8(1.75,-2.425) 17(1.75,2.425) 18(1.25,2.425) 19(0.75,2.425) 20(0.25,2.425) 21(-0.25,2.425) 22(-0.75,2.425) 23(-1.25,2.425) 24(-1.75,2.425)
  oval 0.75x0.3 smd mask+0.05: 9(2.425,-1.75) 10(2.425,-1.25) 11(2.425,-0.75) 12(2.425,-0.25) 13(2.425,0.25) 14(2.425,0.75) 15(2.425,1.25) 16(2.425,1.75) 25(-2.425,1.75) 26(-2.425,1.25) 27(-2.425,0.75) 28(-2.425,0.25) 29(-2.425,-0.25) 30(-2.425,-0.75) 31(-2.425,-1.25) 32(-2.425,-1.75)
  rect 3.7x3.7 smd mask+0.05: 33(0,0)
  silkscreen extent -2.63,-2.63 2.63,2.63, body extent -2.55,-2.55 2.55,2.55, height 1
IMPEDANCE_TABLE [mm]
IND_0805_MURATA_LQM21 [mm] "MCD-02317"
  rect 0.85x1.55 smd mask+0.05: 1(-0.875,0) 2(0.875,0)
  silkscreen extent -0.33,-0.72 0.33,0.72, body extent -1.1,-0.72 1.1,0.72, height 1.45
MIRE_PLACE_SMD_0P8MM [mm]
  round 0.8 smd paste-10 mask+0.2: 1(0,0)
  Top Layer keep-out circle w0.01: c0,0 r0.804
PCB_SPECIFICATIONS [mm]
R0402 [mm]
  rect 0.51x0.7 smd mask+0.05: 1(-0.45,0) 2(0.45,0)
  body extent -0.52,-0.3 0.52,0.3, height 0.4
r0402 [mm]
  rect 0.51x0.7 smd mask+0.05: 1(-0.45,0) 2(0.45,0)
  body extent -0.52,-0.3 0.52,0.3, height 0.4
Sheetbox_4L2S [mil] "Sheetbox 4 layers / 2 silkscreens"
  round 20 on Mech16: 1(813.78,210.69) 1(2736.9,210.69)
SHIELD_HARWIN_S02-20150300_15X20_H3 [mm] "MCD-03126"
  silkscreen extent -7.6,-10.1 7.6,10.1, body extent -7.6,-10.1 7.6,10.1, height 3.25
SOLDER-BRIDGE_R0402-0R [mil] "MCD-01619"
  round 10 smd paste-393.7: 1(-17.72,0) 2(20.67,0)
  Top Layer region: -30.51,-13.78 -30.51,13.78 -8.86,13.78 -2.95,0 -8.86,-13.78
  Top Layer region: 1.48,13.78 8.37,0 1.48,-13.78 30.51,-13.78 30.51,13.78
  silkscreen extent -33,-17 33,17, body extent -20,-12 20,12, height 14
STICKER_BOARD_25X5 [mm] "Sticker to mention board reference + serial number"
  silkscreen extent -12.5,-2.5 12.5,2.5, body extent -12.5,-2.5 12.5,2.5, height 0.01
STICKER_PRODUCT_25X5 [mm] "Sticker to mention board CPN code"
  silkscreen extent -12.5,-2.5 12.5,2.5

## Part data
ANT1: library part MCD-03495, "2.4 GHZ Bluetooth BNRG PCB antenna", Manufacturer=NA
C1: library part MCD-03452, "Capacitor, MLCC, 6.8pF, 50V, C0G, +/-0.05pF, 0402, T=0.5mm", Manufacturer=MURATA, Manufacturer_Part_Number=GJM1555C1H6R8WB01, Package=0402
C2: library part MCD-03662, "Capacitor, MLCC, 0.9pF, 25V, +/-0.05pF, 0402, T=0.5mm", Manufacturer=MURATA, Manufacturer_Part_Number=GRM1555C1ER90WA01D
C3 C6 C10 C11 C12: library part MCD-03442, "Capacitor, MLCC, 100nF, ±10%, X7R, 25V, 0402, T=0.5mm", Manufacturer=MURATA, Manufacturer_Part_Number=GRM155R71E104KE14D, Package=0402
C4: library part MCD-03482, "Capacitor, MLCC, 3pF, COG, 50V, +/-0.1pF, 0402, T=0.5mm", Manufacturer="KYOCERA AVX", Manufacturer_Part_Number=04025A3R0BAT2A, Package=0402
C5: library part MCD-03436, "Capacitor, MLCC, 3pF, COG, 50V, 0402, ±0.1pF, T=0.5mm", Manufacturer=MURATA, Manufacturer_Part_Number=GRM1555C1H3R0BA01D, Package=0402
C7: library part MCD-03543, "Capacitor, MLCC, 20pF, 25V, COG, +/-2%, 0201, T=0.33mm", Manufacturer=MURATA, Manufacturer_Part_Number=GJM0335C1E200GB01
C8 C9: library part MCD-00015, "Capacitor, MLCC, 10pF, 50V, NPO, +/-5%, 0402, T=0.5mm", Manufacturer=YAGEO, Manufacturer_Part_Number=CC0402JRNPO9BN100, Package=0402
C13: library part MCD-03432, "Capacitor, MLCC, 1uF, X7R, 6.3V, 0402, ± 10%, T=0.5mm", Manufacturer=MURATA, Manufacturer_Part_Number=GRM155R70J105KA12, Package=0402
C14 C15: library part MCD-03431, "Capacitor, MLCC, 4.7uF, X5R, 10 V, 0402, ± 20%, T=0.5mm", Manufacturer=MURATA, Manufacturer_Part_Number=GRM155R61A475MEAAD, Package=0402
C16: library part MCD-03483, "Capacitor, MLCC, 0.22uF, X5R, 6.3V, +/-10%, 0402, T=0.5mm", Manufacturer=YAGEO, Manufacturer_Part_Number=CC0402KRX5R5BB224, Package=0402
CN1 CN2: library part MCD-02746, "Header, 25x2, 12.7mm, VR, SMD, T=4.83mm", Manufacturer=SAMTEC
CN3: library part MCD-01531, "Header, 7x2, 1.27mm, VR, T=5.97mm, FTSH series STDC14 without Alignment Pin", Manufacturer=SAMTEC, Manufacturer_Part_Number=FTSH-107-01-L-DV-K
CN4: library part MCD-01583, "Connector_RF, 0Hz to 6GHz, 50R, VR, SMD, T= 1.25mm", Manufacturer=HIROSE
Designator1 Designator2 Designator3: library part MCD-00279
HW1: library part MCD-03126, "RFI shield can, 20x15x3mm", Manufacturer=HARWIN, Package=20x15x3mm
HW2: library part MCD-02189, "Sticker product 25x5 mm", Alternate_Manufacturer=N/A
HW3: library part MCD-02190, "Sticker board 25x5 mm", Alternate_Manufacturer=N/A
JP1: library part MCD-00685, "Header, 3x1, 2.54mm, VR, TH, T=5.84mm/2.54mm", Manufacturer=SAMTEC, Manufacturer_Part_Number=TSW-103-07-F-S
L2: library part MCD-03439, "Inductor, MLCC, 22nH, ±2%, 350mA, 0.58R, 0402, T=1.45mm", Manufacturer=MURATA, Manufacturer_Part_Number=LQG15HN22NG02D, Package=0402
L3: library part MCD-03438, "Inductor, MLCC, 10uH, ±20%, 300mA, 845mR, 0805, T=1.45mm", Manufacturer=MURATA, Manufacturer_Part_Number=LQM21DN100M70L, Package=0805
R1 R2 R10: library part MCD-00052, "Resistor, 0R, 0402, +/-5%, 1/16W", Manufacturer=YAGEO, Manufacturer_Part_Number=RC0402JR-070RL, Package=0402
R3: library part MCD-03301, "Resistor, 100K, 0402, +/-1%, 1/16W", Manufacturer=YAGEO, Manufacturer_Part_Number=RT0402FRE07100KL, Package=0402
R4 R5 R6 R7 R8: library part MCD-00481, "Resistor, 47R, 0402, +/-1%, 1/16W", Manufacturer=YAGEO, Manufacturer_Part_Number=RC0402FR-0747RL, Package=0402
R9: library part MCD-00067, "Resistor, 100R, 0402, +/- 1%, 1/16W", Manufacturer=YAGEO, Manufacturer_Part_Number=RC0402FR-07100RL, Package=0402
SB1 SB2 SB3 SB4 SB5 SB6 SB7 SB8 SB9 SB10 SB11 SB12 SB13 SB14 SB15 SB16 SB17 SB18 SB19 SB20 SB21 SB22 SB23 SB24 SB25 SB28 SB29 SB30 SB31 SB32 SB33 SB34 SB35 SB36 SB37 SB38 SB39 SB40 SB41 SB42 SB43 SB44 SB45 SB46 SB47 SB48 SB49 SB51 SB52 SB53 SB54 SB55 SB56 SB57: library part MCD-01618, "Solder Bridge 0402 ON", Manufacturer=YAGEO, Manufacturer_Part_Number=RC0402JR-070RL, Package=SB0402
SC1 SC2 SC7 SC8: library part MCD-02164, "shield clip Harwin S0981-46R to fix RF shielded cavity - SMT RFI Shield Clip, Corner (T+R)", Manufacturer=HARWIN, Manufacturer_Part_Number=S0981-46R
SC3 SC4 SC5 SC6: library part MCD-01587, "shield clip Harwin S0951-46R to fix RF shielded cavity", Manufacturer=HARWIN, Manufacturer_Part_Number=S0951-46R
U1: library part MCD-03444, "Bluetooth® Low Energy wireless SoC", Manufacturer=STMICROELECTRONICS, Package=QFN32
U2: library part MCD-03490, "2.4 GHz low pass filter matched to BLUENRG-LP-LPS", Manufacturer=STMICROELECTRONICS, Manufacturer_Part_Number=MLPF-NRG-01D3, Package=CSP
X1: library part MCD-01446, "Crystal, 32MHz, 8pF, +/-10ppm, 60R, 2x1.6mm", Manufacturer=NDK, Manufacturer_Part_Number=NX2016SA-32MHZ-EXS00A-CS06654, Package=2x1.6mm
X2: library part MCD-01445, "Crystal, 32.768kHz, 7pF, +/-20ppm, 80K, 2.05x1.2mm", Manufacturer=NDK, Manufacturer_Part_Number=NX2012SA-32.768KHZ-EXS00A-MU00389, Package=2.05x1.2mm

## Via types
v1: diameter 0.6, hole 0.3, Top Layer to Bottom Layer, tented both sides, 564 vias
v2: diameter 0.45, hole 0.2, Top Layer to Bottom Layer, tented both sides, 17 vias

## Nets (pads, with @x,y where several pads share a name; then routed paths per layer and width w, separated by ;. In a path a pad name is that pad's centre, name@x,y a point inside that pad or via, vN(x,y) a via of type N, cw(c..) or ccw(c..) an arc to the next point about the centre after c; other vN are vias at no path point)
ARD_A0: CN1.24 SB4.1 SB15.2 | length 4.6
  Bottom Layer w0.127: CN1.24@6.401,19.818 8.393,19.818 8.825,20.25 SB4.1@9.55,20.25 SB15.2@9.55,21.4 ; SB15.2@9.525,21.5 9.499,21.474 9.499,21.441 SB15.2@9.545,21.395
ARD_A1: CN1.26 SB13.2 | length 3.3
  Bottom Layer w0.127: CN1.26@6.401,18.548 8.073,18.548 8.525,19 SB13.2@9.475,19
ARD_A2: CN1.36 SB5.2 SB10.2 SB30.1 | length 7.6
  Top Layer w0.127: v1(8.3,12.175) 8.813,12.688 8.813,13.662 8.775,13.7 v1(8.775,14.475)
  Bottom Layer w0.127: CN1.36@6.42,12.177 8.298,12.177 v1(8.3,12.175) ; v1(8.775,14.475) 9.475,14.475 ; SB10.2@9.475,16.5 SB5.2@9.475,15.25 9.475,14.475 ; SB30.1@9.55,14.075 9.475,14.15 9.475,14.475
ARD_A3: CN1.38 SB8.2 SB19.1 | length 4.4
  Bottom Layer w0.127: CN1.38@6.401,10.928 8.278,10.928 8.85,11.5 SB8.2@9.475,11.5 9.475,11.534 9.55,11.609 SB19.1@9.55,12.575
ARD_A4: CN1.42 SB21.2 SB25.1 | length 4.6
  Bottom Layer w0.127: CN1.42@6.401,8.388 8.238,8.388 8.825,8.975 SB25.1@9.435,8.975 ; SB25.1@9.436,8.976 SB25.1@9.549,8.976 ; SB21.2@9.525,10.2 9.55,10.175 SB25.1@9.55,9
ARD_A5: CN1.44 SB18.2 SB23.1 | length 4.6
  Bottom Layer w0.127: CN1.44@6.401,7.118 8.168,7.118 8.775,7.725 SB18.2@9.36,7.725 ; SB18.2@9.361,7.726 SB18.2@9.474,7.726 ; SB18.2@9.475,7.75 9.475,7.725 9.475,6.475 SB23.1@9.5,6.45
ARD_D2: CN2.41 SB36.2 | length 3.4
  Bottom Layer w0.127: 33.9,9.65 34,9.75 34.2,9.75 35.255,8.695 36.33,8.695 CN2.41@36.65,8.375
ARD_D3: CN2.39 SB24.2 | length 2.5
  Bottom Layer w0.127: 33.875,10.85 35.075,9.65 CN2.39@35.85,9.65
ARD_D4: CN2.37 SB44.1 | length 3.1
  Bottom Layer w0.127: 33.9,13.325 33.9,13.25 34.75,12.4 34.75,11.75 35.265,11.235 35.29,11.235 35.575,10.95 CN2.37@35.575,10.925
ARD_D5: CN2.35 SB42.2 | length 3.3
  Bottom Layer w0.127: SB42.2@33.775,14.75 34.775,13.75 34.775,13 35.27,12.505 35.29,12.505 35.575,12.22 CN2.35@35.575,12.2
ARD_D6: CN2.29 SB40.2 | length 2.6
  Bottom Layer w0.127: 33.875,17.075 34.95,16 CN2.29@36,16
ARD_D7: CN2.27 SB39.1 | length 1.7
  Bottom Layer w0.127: 33.95,18.425 34.425,18.425 35.265,17.585 35.29,17.585 35.3,17.575 CN2.27@35.3,17.55
ARD_D8: CN2.25 U1.18 | length 37.7
  Top Layer w0.127: v1(16.3,33) 16.813,33.513 17.263,33.513 17.276,33.5 U1.18@17.825,33.5 ; v1(16.375,19.112) 17.062,19.112 17.298,19.348 20.31,19.348 20.329,19.329 ; 20.325,19.325 20.627,19.023 26.177,19.023 26.65,18.55 29.6,18.55 v1(29.625,18.575)
  Bottom Layer w0.127: v1(16.3,33) 15.225,31.925 15.225,28.521 16.375,27.371 v1(16.375,19.112) ; v1(29.625,18.575) 29.652,18.548 31.098,18.548 31.675,19.125 34.35,19.125 34.927,18.548 CN2.25@36.621,18.548
ARD_D9: CN2.23 SB12.1 | length 2.9
  Bottom Layer w0.127: SB12.1@33.7,19.75 34.775,19.75 34.843,19.818 CN2.23@36.621,19.818
ARD_D10: CN2.21 SB47.1 | length 2.9
  Bottom Layer w0.127: SB47.1@33.725,21 34.85,21 34.938,21.088 CN2.21@36.621,21.088
ARD_D11: CN2.15 SB22.2 SB43.1 | length 4.2
  Bottom Layer w0.127: SB43.1@33.724,24.691 33.775,24.641 SB22.2@33.775,23.5 ; SB43.1@33.725,24.775 33.75,24.75 34.25,24.75 34.398,24.898 CN2.15@36.621,24.898
ARD_D12: CN2.13 SB41.1 | length 3
  Bottom Layer w0.127: SB41.1@33.7,26 34.325,26 34.493,26.168 CN2.13@36.621,26.168
ARD_D13: CN2.11 SB14.2 | length 2.9
  Bottom Layer w0.127: SB14.2@33.775,27.25 34.625,27.25 34.813,27.438 CN2.11@36.621,27.438
ARD_D14: CN2.9 SB34.2 | length 3.5
  Bottom Layer w0.127: SB34.2@33.775,29.75 34.375,29.75 34.725,29.4 34.725,29 35.017,28.708 CN2.9@36.621,28.708
ARD_D15: CN2.7 SB32.2 | length 3.2
  Bottom Layer w0.127: SB32.2@33.775,31 34.8,29.975 CN2.7@36.6,29.975
BOOT0: CN1.9 JP1.2 SB48.1 | length 37.7
  Bottom Layer w0.127: CN1.9@2.331,28.708 3.883,28.708 4.763,29.588 4.763,30.464 4.925,30.625 8.625,30.625 8.75,30.5 SB48.1@9.55,30.5 9.55,31.442 10.748,32.64 10.748,34.315 11.658,35.225 13.525,35.225 15.025,33.725 15.825,33.725 16.55,34.45 17.875,34.45 18.175,34.75 21.175,34.75 21.75,35.325 21.75,36.013 22.61,36.873 24.585,36.873 25.083,36.375 26.025,36.375 26.027,36.373 27.402,36.373 28.887,34.888 28.887,34.363 JP1.2@30.75,32.5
